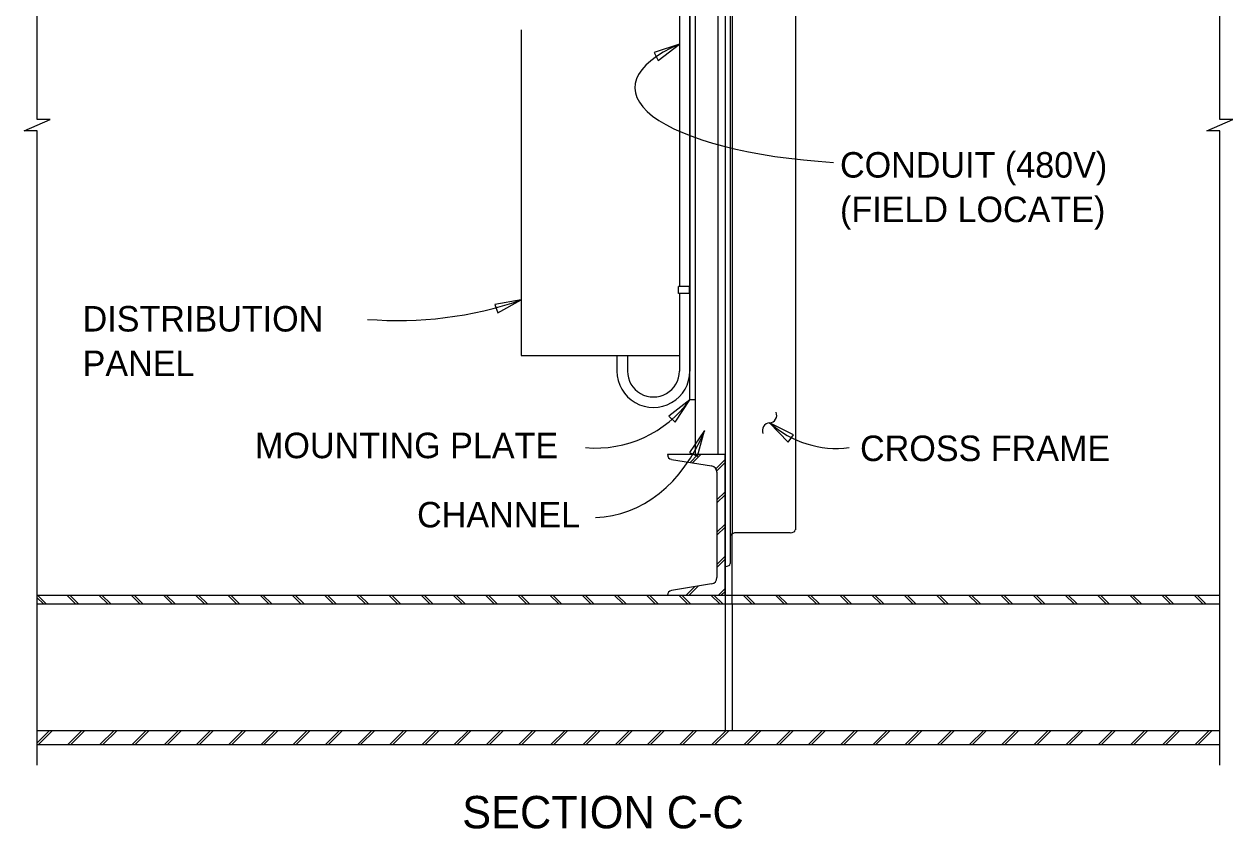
# Model space of a CAD drawing. Extents: x 927736.2 to 927809.6, y 636703.6 to 636757.7.
# Drawn here: x 927786.14 to 927803.81, y 636736.85 to 636748.62 of the extents above; entities that cross this region are included whole.
import ezdxf

# ---------------------------------------------------------------- set-up
doc = ezdxf.new("R2010")
doc.units = 0
for name, color, linetype in [('Default', 7, 'Continuous'), ('DimLines_dp', 7, 'Continuous'), ('Miscellaneous1', 7, 'Continuous'), ('Miscellaneous3', 7, 'Continuous')]:
    doc.layers.add(name, color=color, linetype=linetype)

msp = doc.modelspace()

# ---------------------------------------------------------------- linework, layer by layer
at = {"layer": 'Default'}
msp.add_line((927795.875, 636749.822), (927795.875, 636743.545), dxfattribs=at)
at = {"layer": 'DimLines_dp'}
for points in [[(927786.333, 636737.782), (927786.333, 636747.055), (927786.142, 636747.055), (927786.333, 636747.139), (927786.524, 636747.222), (927786.333, 636747.222), (927786.333, 636756.484)], [(927803.622, 636737.782), (927803.622, 636747.055), (927803.431, 636747.055), (927803.622, 636747.139), (927803.813, 636747.222), (927803.622, 636747.222), (927803.622, 636749.203)]]:
    msp.add_lwpolyline(points, dxfattribs=at)
for points in [[(927795.721, 636748.326), (927795.351, 636748.201), (927795.412, 636748.086)], [(927793.408, 636744.584), (927793.023, 636744.52), (927793.065, 636744.397)], [(927795.875, 636743.124), (927795.566, 636742.885), (927795.662, 636742.796)], [(927796.091, 636742.677), (927795.867, 636742.356), (927795.985, 636742.3)], [(927797.041, 636742.789), (927797.312, 636742.507), (927797.389, 636742.612)]]:
    msp.add_lwpolyline(points, close=True, dxfattribs=at)
for centre, radius, start, end in [((927791.608, 636749.822), 5.539, 265.3641, 288.9731), ((927794.495, 636744.121), 1.702, 265.0985, 324.1488), ((927797.035, 636742.898), 0.11, 272.3583, 24.0855), ((927797.044, 636742.677), 0.11, 92.3583, 204.0855), ((927798.022, 636743.886), 1.472, 228.179, 277.0931)]:
    msp.add_arc(centre, radius, start, end, dxfattribs=at)
for centre, major_axis, ratio, start_param, end_param in [((927798.697, 636747.688), (3.627, 0), 0.307602, 2.532927, 4.511363), ((927794.459, 636743.844), (-0.036, 2.438), 0.759061, 3.141594, 4.201813)]:
    msp.add_ellipse(centre, major_axis=major_axis, ratio=ratio, start_param=start_param, end_param=end_param, dxfattribs=at)
at = {"layer": 'Miscellaneous1'}
for p, q in [((927795.721, 636749.485), (927795.721, 636744.78)), ((927795.721, 636744.677), (927795.721, 636743.545)), ((927794.808, 636743.771), (927794.808, 636743.545)), ((927794.962, 636743.771), (927794.962, 636743.545))]:
    msp.add_line(p, q, dxfattribs=at)
for points in [[(927795.875, 636743.771), (927795.875, 636750.493), (927793.408, 636750.493), (927793.408, 636750.124)], [(927793.408, 636748.533), (927793.408, 636743.771), (927795.721, 636743.771)]]:
    msp.add_lwpolyline(points, dxfattribs=at)
for radius in [0.533, 0.379]:
    msp.add_arc((927795.342, 636743.545), radius, 180, 0.008, dxfattribs=at)
at = {"layer": 'Miscellaneous3'}
for p, q in [((927796.286, 636753.27), (927796.286, 636742.324)), ((927796.492, 636753.237), (927796.492, 636741.164)), ((927797.417, 636753.237), (927797.417, 636741.222)), ((927796.466, 636752.744), (927796.466, 636740.73)), ((927796.389, 636752.319), (927796.389, 636740.268)), ((927795.875, 636744.78), (927795.708, 636744.78)), ((927795.708, 636744.677), (927795.708, 636744.78)), ((927795.862, 636744.78), (927795.862, 636744.677)), ((927795.875, 636744.677), (927795.708, 636744.677)), ((927795.952, 636743.124), (927795.952, 636742.324)), ((927796.389, 636742.324), (927795.546, 636742.324)), ((927795.55, 636742.31), (927795.564, 636742.324)), ((927795.877, 636742.21), (927795.992, 636742.324)), ((927795.915, 636742.203), (927796.035, 636742.324)), ((927796.389, 636740.268), (927796.389, 636742.324)), ((927795.605, 636742.254), (927796.193, 636742.158)), ((927796.254, 636742.115), (927796.389, 636742.25)), ((927796.267, 636742.085), (927796.389, 636742.206)), ((927796.271, 636742.067), (927796.271, 636740.525)), ((927796.271, 636741.661), (927796.389, 636741.779)), ((927796.271, 636741.617), (927796.389, 636741.735)), ((927796.271, 636741.19), (927796.389, 636741.308)), ((927796.271, 636741.146), (927796.389, 636741.265)), ((927796.492, 636740.268), (927796.492, 636741.164)), ((927797.339, 636741.182), (927796.569, 636741.182)), ((927796.271, 636740.719), (927796.389, 636740.837)), ((927796.271, 636740.675), (927796.389, 636740.794)), ((927796.193, 636740.434), (927795.605, 636740.338)), ((927795.82, 636740.268), (927795.945, 636740.393)), ((927795.863, 636740.268), (927795.997, 636740.402)), ((927796.291, 636740.268), (927796.389, 636740.366)), ((927786.333, 636740.268), (927803.622, 636740.268)), ((927786.422, 636740.14), (927786.333, 636740.229)), ((927786.465, 636740.14), (927786.337, 636740.268)), ((927786.893, 636740.14), (927786.764, 636740.268)), ((927786.936, 636740.14), (927786.808, 636740.268)), ((927787.364, 636740.14), (927787.235, 636740.268)), ((927787.407, 636740.14), (927787.279, 636740.268)), ((927787.834, 636740.14), (927787.706, 636740.268)), ((927787.878, 636740.14), (927787.749, 636740.268)), ((927788.305, 636740.14), (927788.177, 636740.268)), ((927788.349, 636740.14), (927788.22, 636740.268)), ((927788.776, 636740.14), (927788.648, 636740.268)), ((927788.82, 636740.14), (927788.691, 636740.268)), ((927789.247, 636740.14), (927789.119, 636740.268)), ((927789.291, 636740.14), (927789.162, 636740.268)), ((927789.718, 636740.14), (927789.59, 636740.268)), ((927789.762, 636740.14), (927789.633, 636740.268)), ((927790.189, 636740.14), (927790.061, 636740.268)), ((927790.233, 636740.14), (927790.104, 636740.268)), ((927790.66, 636740.14), (927790.531, 636740.268)), ((927790.704, 636740.14), (927790.575, 636740.268)), ((927791.131, 636740.14), (927791.002, 636740.268)), ((927791.175, 636740.14), (927791.046, 636740.268)), ((927791.602, 636740.14), (927791.473, 636740.268)), ((927791.646, 636740.14), (927791.517, 636740.268)), ((927792.073, 636740.14), (927791.944, 636740.268)), ((927792.116, 636740.14), (927791.988, 636740.268)), ((927792.544, 636740.14), (927792.415, 636740.268)), ((927792.587, 636740.14), (927792.459, 636740.268)), ((927793.015, 636740.14), (927792.886, 636740.268)), ((927793.058, 636740.14), (927792.93, 636740.268)), ((927793.486, 636740.14), (927793.357, 636740.268)), ((927793.529, 636740.14), (927793.401, 636740.268)), ((927793.957, 636740.14), (927793.828, 636740.268)), ((927794, 636740.14), (927793.872, 636740.268)), ((927794.428, 636740.14), (927794.299, 636740.268)), ((927794.471, 636740.14), (927794.343, 636740.268)), ((927794.898, 636740.14), (927794.77, 636740.268)), ((927794.942, 636740.14), (927794.813, 636740.268)), ((927795.369, 636740.14), (927795.241, 636740.268)), ((927795.413, 636740.14), (927795.284, 636740.268)), ((927795.546, 636740.268), (927796.389, 636740.268)), ((927795.84, 636740.14), (927795.712, 636740.268)), ((927795.884, 636740.14), (927795.755, 636740.268)), ((927796.311, 636740.14), (927796.183, 636740.268)), ((927796.355, 636740.14), (927796.226, 636740.268)), ((927796.334, 636740.268), (927796.389, 636740.323)), ((927796.389, 636740.268), (927796.389, 636740.14)), ((927796.492, 636740.14), (927796.492, 636740.268)), ((927796.782, 636740.14), (927796.654, 636740.268)), ((927796.826, 636740.14), (927796.697, 636740.268)), ((927797.253, 636740.14), (927797.125, 636740.268)), ((927797.297, 636740.14), (927797.168, 636740.268)), ((927797.724, 636740.14), (927797.595, 636740.268)), ((927797.768, 636740.14), (927797.639, 636740.268)), ((927798.195, 636740.14), (927798.066, 636740.268)), ((927798.239, 636740.14), (927798.11, 636740.268)), ((927798.666, 636740.14), (927798.537, 636740.268)), ((927798.71, 636740.14), (927798.581, 636740.268)), ((927799.137, 636740.14), (927799.008, 636740.268)), ((927799.18, 636740.14), (927799.052, 636740.268)), ((927799.608, 636740.14), (927799.479, 636740.268)), ((927799.651, 636740.14), (927799.523, 636740.268)), ((927800.079, 636740.14), (927799.95, 636740.268)), ((927800.122, 636740.14), (927799.994, 636740.268)), ((927800.55, 636740.14), (927800.421, 636740.268)), ((927800.593, 636740.14), (927800.465, 636740.268)), ((927801.021, 636740.14), (927800.892, 636740.268)), ((927801.064, 636740.14), (927800.936, 636740.268)), ((927801.492, 636740.14), (927801.363, 636740.268)), ((927801.535, 636740.14), (927801.407, 636740.268)), ((927801.962, 636740.14), (927801.834, 636740.268)), ((927802.006, 636740.14), (927801.878, 636740.268)), ((927802.433, 636740.14), (927802.305, 636740.268)), ((927802.477, 636740.14), (927802.348, 636740.268)), ((927802.904, 636740.14), (927802.776, 636740.268)), ((927802.948, 636740.14), (927802.819, 636740.268)), ((927803.375, 636740.14), (927803.247, 636740.268)), ((927803.419, 636740.14), (927803.29, 636740.268)), ((927786.333, 636740.14), (927803.622, 636740.14)), ((927796.389, 636740.14), (927796.389, 636738.29)), ((927796.492, 636740.14), (927796.492, 636738.29)), ((927786.333, 636738.29), (927803.622, 636738.29)), ((927786.333, 636738.109), (927786.514, 636738.29)), ((927786.352, 636738.084), (927786.557, 636738.29)), ((927786.779, 636738.084), (927786.985, 636738.29)), ((927786.823, 636738.084), (927787.028, 636738.29)), ((927787.25, 636738.084), (927787.456, 636738.29)), ((927787.294, 636738.084), (927787.499, 636738.29)), ((927787.721, 636738.084), (927787.926, 636738.29)), ((927787.765, 636738.084), (927787.97, 636738.29)), ((927788.192, 636738.084), (927788.397, 636738.29)), ((927788.236, 636738.084), (927788.441, 636738.29)), ((927788.663, 636738.084), (927788.868, 636738.29)), ((927788.707, 636738.084), (927788.912, 636738.29)), ((927789.134, 636738.084), (927789.339, 636738.29)), ((927789.177, 636738.084), (927789.383, 636738.29)), ((927789.605, 636738.084), (927789.81, 636738.29)), ((927789.648, 636738.084), (927789.854, 636738.29)), ((927790.076, 636738.084), (927790.281, 636738.29)), ((927790.119, 636738.084), (927790.325, 636738.29)), ((927790.547, 636738.084), (927790.752, 636738.29)), ((927790.59, 636738.084), (927790.796, 636738.29)), ((927791.018, 636738.084), (927791.223, 636738.29)), ((927791.061, 636738.084), (927791.267, 636738.29)), ((927791.489, 636738.084), (927791.694, 636738.29)), ((927791.532, 636738.084), (927791.738, 636738.29)), ((927791.959, 636738.084), (927792.165, 636738.29)), ((927792.003, 636738.084), (927792.208, 636738.29)), ((927792.43, 636738.084), (927792.636, 636738.29)), ((927792.474, 636738.084), (927792.679, 636738.29)), ((927792.901, 636738.084), (927793.107, 636738.29)), ((927792.945, 636738.084), (927793.15, 636738.29)), ((927793.372, 636738.084), (927793.578, 636738.29)), ((927793.416, 636738.084), (927793.621, 636738.29)), ((927793.843, 636738.084), (927794.049, 636738.29)), ((927793.887, 636738.084), (927794.092, 636738.29)), ((927794.314, 636738.084), (927794.52, 636738.29)), ((927794.358, 636738.084), (927794.563, 636738.29)), ((927794.785, 636738.084), (927794.99, 636738.29)), ((927794.829, 636738.084), (927795.034, 636738.29)), ((927795.256, 636738.084), (927795.461, 636738.29)), ((927795.3, 636738.084), (927795.505, 636738.29)), ((927795.727, 636738.084), (927795.932, 636738.29)), ((927795.771, 636738.084), (927795.976, 636738.29)), ((927796.198, 636738.084), (927796.403, 636738.29)), ((927796.241, 636738.084), (927796.447, 636738.29)), ((927796.669, 636738.084), (927796.874, 636738.29)), ((927796.712, 636738.084), (927796.918, 636738.29)), ((927797.14, 636738.084), (927797.345, 636738.29)), ((927797.183, 636738.084), (927797.389, 636738.29)), ((927797.611, 636738.084), (927797.816, 636738.29)), ((927797.654, 636738.084), (927797.86, 636738.29)), ((927798.082, 636738.084), (927798.287, 636738.29)), ((927798.125, 636738.084), (927798.331, 636738.29)), ((927798.553, 636738.084), (927798.758, 636738.29)), ((927798.596, 636738.084), (927798.802, 636738.29)), ((927799.023, 636738.084), (927799.229, 636738.29)), ((927799.067, 636738.084), (927799.272, 636738.29)), ((927799.494, 636738.084), (927799.7, 636738.29)), ((927799.538, 636738.084), (927799.743, 636738.29)), ((927799.965, 636738.084), (927800.171, 636738.29)), ((927800.009, 636738.084), (927800.214, 636738.29)), ((927800.436, 636738.084), (927800.642, 636738.29)), ((927800.48, 636738.084), (927800.685, 636738.29)), ((927800.907, 636738.084), (927801.113, 636738.29)), ((927800.951, 636738.084), (927801.156, 636738.29)), ((927801.378, 636738.084), (927801.584, 636738.29)), ((927801.422, 636738.084), (927801.627, 636738.29)), ((927801.849, 636738.084), (927802.055, 636738.29)), ((927801.893, 636738.084), (927802.098, 636738.29)), ((927802.32, 636738.085), (927802.525, 636738.29)), ((927802.364, 636738.085), (927802.569, 636738.29)), ((927802.791, 636738.085), (927802.996, 636738.29)), ((927802.835, 636738.085), (927803.04, 636738.29)), ((927803.262, 636738.085), (927803.467, 636738.29)), ((927803.306, 636738.085), (927803.511, 636738.29)), ((927786.333, 636738.084), (927803.622, 636738.084))]:
    msp.add_line(p, q, dxfattribs=at)
msp.add_lwpolyline([(927795.875, 636751.141), (927795.952, 636751.141), (927795.952, 636743.124), (927795.875, 636743.124)], close=True, dxfattribs=at)
for centre, radius, start, end in [((927795.617, 636742.324), 0.0705, 180, 260.5), ((927796.178, 636742.067), 0.0925, 360, 80.5), ((927796.178, 636740.525), 0.0925, 279.5, 360), ((927795.617, 636740.268), 0.0705, 99.5, 180)]:
    msp.add_arc(centre, radius, start, end, dxfattribs=at)
for centre, major_axis, end_param in [((927796.569, 636741.129), (-0.103, 0), 6.283185), ((927797.339, 636741.222), (0.0771, 0), 6.283185), ((927796.389, 636740.73), (0.0771, 0), 6.270045)]:
    msp.add_ellipse(centre, major_axis=major_axis, ratio=0.5176, start_param=4.712389, end_param=end_param, dxfattribs=at)

# ---------------------------------------------------------------- texts
at = {"layer": 'Default'}
msp.add_text('SECTION C-C', height=0.4736, dxfattribs=at).set_placement((927792.546, 636736.86))
at = {"layer": 'DimLines_dp'}
for s, height, p in [('CONDUIT (480V)', 0.37296, (927798.07, 636746.373)), ('(FIELD LOCATE)', 0.37296, (927798.07, 636745.722)), ('DISTRIBUTION ', 0.37296, (927786.996, 636744.123)), ('PANEL', 0.373, (927786.996, 636743.471)), ('MOUNTING PLATE', 0.37296, (927789.516, 636742.271)), ('CROSS FRAME', 0.37296, (927798.363, 636742.229)), ('CHANNEL', 0.373, (927791.886, 636741.259))]:
    msp.add_text(s, height=height, dxfattribs=at).set_placement(p)

doc.saveas('drawing.dxf')
